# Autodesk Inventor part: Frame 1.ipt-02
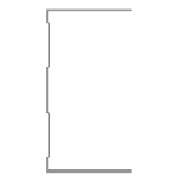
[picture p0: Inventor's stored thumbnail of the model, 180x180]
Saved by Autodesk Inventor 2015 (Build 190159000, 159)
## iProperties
IsCustomPart: 1
Created: 2015-04
Part Number: Frame 1.ipt-02
Material: Aluminum 6061
Description: Kévin Novo
Document SubType Name: Modeling
Standard: Kevin
Designer: suporte
Standards Organization: Kevin
Language: en-US
Size Designation: (Unnamed 2)
Categories: <MemberInstance><Categories><Category DisplayName="Structural Shapes" InternalName="089c4875-fa83-4c05-b084-43b9cc11f5ed" Mnemonic="GRDR"><CategoryParameter Dis
Density: 2.7 g/cm^3
Appearance: Aluminum - Flat
_CCFamilyMember: 2
_CCFamilyDisplayName: Kévin - Kévin Novo
_FrameMemberDoc: Frame Member File
_Version: 15.0.0
_GetPNFromCC: 1
G_W: 50,000 mm
G_H: 75,000 mm
G_L: 398,157 mm
Author: suporte
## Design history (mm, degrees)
node "Start Plane"
node "End Plane"
sketch "Sketch"
  geometry: L1 (24.7, 37.5)-(24.7, 36.9); L2 (24.7, 36.9)-(-24.7, 36.9); L3 (-24.7, -36.9)-(24.7, -36.9); L4 (24.7, -36.9)-(24.7, -37.5); L5 (24.7, -37.5)-(-25.3, -37.5); L6 (-25.3, 37.5)-(24.7, 37.5); L7 (-24.7, 36.9)-(-24.7, 31.9); L8 (-24.7, 31.9)-(-23.3, 30.5); L9 (-23.3, 30.5)-(-23.3, 10.934); L10 (-23.3, 10.934)-(-24.7, 9.534); L11 (-24.7, 9.534)-(-24.7, -9.534); L12 (-24.7, -9.534)-(-23.3, -10.934); L13 (-23.3, -10.934)-(-23.3, -30.5); L14 (-23.3, -30.5)-(-24.7, -31.9); L15 (-24.7, -31.9)-(-24.7, -36.9); L16 (-25.3, -37.5)-(-25.3, -31.651); L17 (-25.3, -31.651)-(-23.9, -30.251); L18 (-23.9, -30.251)-(-23.9, -11.183); L19 (-23.9, -11.183)-(-25.3, -9.783); L20 (-25.3, -9.783)-(-25.3, 9.783); L21 (-25.3, 9.783)-(-23.9, 11.183); L22 (-23.9, 11.183)-(-23.9, 30.251); L23 (-23.9, 30.251)-(-25.3, 31.651); L24 (-25.3, 31.651)-(-25.3, 37.5); L25 (-25.3, 0)-(30.37, 0); 3 further points
  constraints: 50 end point, 10 point on line, 9 parallel, 5 perpendicular, 4 equal length, 3 midpoint, 3 vertical, 2 vertical alignment, 1 collinear, 1 horizontal, 1 horizontal alignment
  dimensions: "d3" = 0.6 distance of L1.start L1.end (= d6); "d5" = 75 distance between parallel lines of L5 L6; "d6" = 0.6 distance between parallel lines of L24 L7 (= d8); "d7" = 0.6 distance between parallel lines of L8 L23 (= d8); "d8" = 0.6 distance between parallel lines of L22 L9 (= d12); "Espessura" = 0.6 distance between parallel lines of L17 L14; "d10" = 0.6 distance between parallel lines of L13 L18 (= Espessura); "d11" = 0.6 distance between parallel lines of L12 L19 (= Espessura); "d12" = 0.6 distance between parallel lines of L21 L10 (= d11); "d13" = 5 distance of L2.end L7.end; "d15" = 135 deg angle of L9 L8; "d16" = 2 distance between parallel lines of L24 L9; "d17" = 50 distance of L6.start L1.start
extrude "Body" join sketch "Sketch" stored distance "d24" = 0.13; taper "d25" = 0 deg
node "Driven Length"
  sketch "Sketch10"
    geometry: L1 (0, 0)-(10, 0) reference
    constraints: 2 end point, 1 horizontal
  workplane "Work Plane7"
  sketch "Sketch11"
    geometry: L1 (-2, 0)-(12, 0) reference; L2 (-2, 398.157)-(12, 398.157) reference
    dimensions: "d27" = 398.15728 distance between parallel lines of L1 L2 (derived)
body "Solid1"
other parameters: "tamanho" = 398.15728, "G_OFFSET_START" = 0 [user parameter; used in 1 equation term], "G_OFFSET_END" = 0 [user parameter; used in 1 equation term], "d22" = 0 (computed from G_OFFSET_START), "d23" = 398.15728 (= tamanho + G_OFFSET_END), "G_L" = 398.15728 (= d27) [user parameter], "d34" = 90 deg
